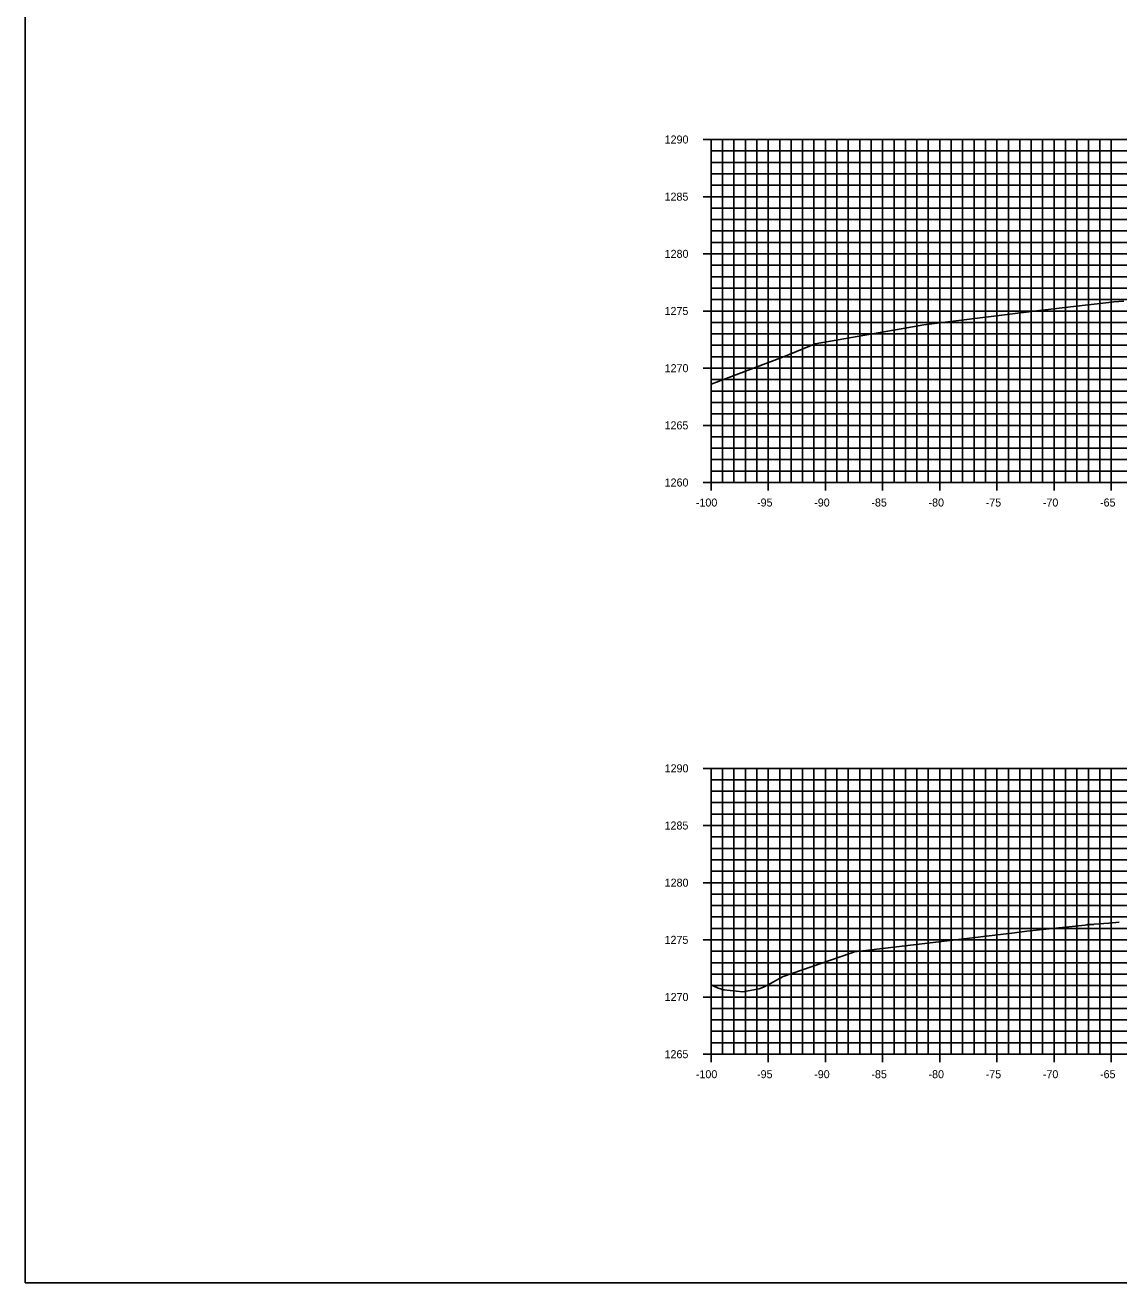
# Model space of a CAD drawing. Extents: x 674939 to 678919, y 750652 to 765176.
# Drawn here: x 678578.5 to 678674.2, y 756212.6 to 756322.6 of the extents above; entities that cross this region are included whole.
import ezdxf

# ---------------------------------------------------------------- set-up
doc = ezdxf.new("R2010")
doc.units = 0
for name, color, linetype in [('Level 10', 7, 'Continuous'), ('Level 20', 7, 'Continuous'), ('Level 4', 7, 'Continuous'), ('Level 8', 7, 'Continuous'), ('Level 9', 7, 'Continuous')]:
    doc.layers.add(name, color=color, linetype=linetype)

msp = doc.modelspace()

# ---------------------------------------------------------------- linework, layer by layer
at = {"layer": 'Level 10'}
for points in [[(678638.53, 756291.15), (678644.85, 756293.54), (678647.63, 756294.67), (678655.17, 756295.98), (678657.14, 756296.33), (678657.84, 756296.42), (678667.03, 756297.57), (678669.97, 756297.92), (678673.58, 756298.32), (678673.75, 756298.34), (678674.63, 756298.4)], [(678638.53, 756238.63), (678638.71, 756238.54), (678639.14, 756238.31), (678639.64, 756238.18), (678641.3, 756238), (678642.73, 756238.28), (678643.12, 756238.41), (678643.41, 756238.57), (678644.83, 756239.35), (678650.67, 756241.35), (678651.07, 756241.49), (678665.08, 756243.17), (678666.15, 756243.31), (678668.11, 756243.52), (678671.25, 756243.84), (678671.39, 756243.87), (678671.47, 756243.88), (678672.01, 756243.9), (678672.05, 756243.91), (678673.31, 756244.02), (678674.22, 756244.09)]]:
    msp.add_lwpolyline(points, dxfattribs=at)
at = {"layer": 'Level 20'}
for p, q in [((678638.53, 756312.55), (678838.53, 756312.55)), ((678638.53, 756282.55), (678638.53, 756312.55)), ((678639.53, 756282.55), (678639.53, 756312.55)), ((678640.53, 756282.55), (678640.53, 756312.55)), ((678641.53, 756282.55), (678641.53, 756312.55)), ((678642.53, 756282.55), (678642.53, 756312.55)), ((678643.53, 756282.55), (678643.53, 756312.55)), ((678644.53, 756282.55), (678644.53, 756312.55)), ((678645.53, 756282.55), (678645.53, 756312.55)), ((678646.53, 756282.55), (678646.53, 756312.55)), ((678647.53, 756282.55), (678647.53, 756312.55)), ((678648.53, 756282.55), (678648.53, 756312.55)), ((678649.53, 756282.55), (678649.53, 756312.55)), ((678650.53, 756282.55), (678650.53, 756312.55)), ((678651.53, 756282.55), (678651.53, 756312.55)), ((678652.53, 756282.55), (678652.53, 756312.55)), ((678653.53, 756282.55), (678653.53, 756312.55)), ((678654.53, 756282.55), (678654.53, 756312.55)), ((678655.53, 756282.55), (678655.53, 756312.55)), ((678656.53, 756282.55), (678656.53, 756312.55)), ((678657.53, 756282.55), (678657.53, 756312.55)), ((678658.53, 756282.55), (678658.53, 756312.55)), ((678659.53, 756282.55), (678659.53, 756312.55)), ((678660.53, 756282.55), (678660.53, 756312.55)), ((678661.53, 756282.55), (678661.53, 756312.55)), ((678662.53, 756282.55), (678662.53, 756312.55)), ((678663.53, 756282.55), (678663.53, 756312.55)), ((678664.53, 756282.55), (678664.53, 756312.55)), ((678665.53, 756282.55), (678665.53, 756312.55)), ((678666.53, 756282.55), (678666.53, 756312.55)), ((678667.53, 756282.55), (678667.53, 756312.55)), ((678668.53, 756282.55), (678668.53, 756312.55)), ((678669.53, 756282.55), (678669.53, 756312.55)), ((678670.53, 756282.55), (678670.53, 756312.55)), ((678671.53, 756282.55), (678671.53, 756312.55)), ((678672.53, 756282.55), (678672.53, 756312.55)), ((678673.53, 756282.55), (678673.53, 756312.55)), ((678638.53, 756311.55), (678838.53, 756311.55)), ((678638.53, 756310.55), (678838.53, 756310.55)), ((678638.53, 756309.55), (678838.53, 756309.55)), ((678638.53, 756308.55), (678838.53, 756308.55)), ((678638.53, 756307.55), (678838.53, 756307.55)), ((678638.53, 756306.55), (678838.53, 756306.55)), ((678638.53, 756305.55), (678838.53, 756305.55)), ((678638.53, 756304.55), (678838.53, 756304.55)), ((678638.53, 756303.55), (678838.53, 756303.55)), ((678638.53, 756302.55), (678838.53, 756302.55)), ((678638.53, 756301.55), (678838.53, 756301.55)), ((678638.53, 756300.55), (678838.53, 756300.55)), ((678638.53, 756299.55), (678838.53, 756299.55)), ((678638.53, 756298.55), (678838.53, 756298.55)), ((678638.53, 756297.55), (678838.53, 756297.55)), ((678638.53, 756296.55), (678838.53, 756296.55)), ((678638.53, 756295.55), (678838.53, 756295.55)), ((678638.53, 756294.55), (678838.53, 756294.55)), ((678638.53, 756293.55), (678838.53, 756293.55)), ((678638.53, 756292.55), (678838.53, 756292.55)), ((678638.53, 756291.55), (678838.53, 756291.55)), ((678638.53, 756290.55), (678838.53, 756290.55)), ((678638.53, 756289.55), (678838.53, 756289.55)), ((678638.53, 756288.55), (678838.53, 756288.55)), ((678638.53, 756287.55), (678838.53, 756287.55)), ((678638.53, 756286.55), (678838.53, 756286.55)), ((678638.53, 756285.55), (678838.53, 756285.55)), ((678638.53, 756284.55), (678838.53, 756284.55)), ((678638.53, 756283.55), (678838.53, 756283.55)), ((678638.53, 756282.55), (678838.53, 756282.55)), ((678638.53, 756257.55), (678838.53, 756257.55)), ((678638.53, 756232.55), (678638.53, 756257.55)), ((678639.53, 756232.55), (678639.53, 756257.55)), ((678640.53, 756232.55), (678640.53, 756257.55)), ((678641.53, 756232.55), (678641.53, 756257.55)), ((678642.53, 756232.55), (678642.53, 756257.55)), ((678643.53, 756232.55), (678643.53, 756257.55)), ((678644.53, 756232.55), (678644.53, 756257.55)), ((678645.53, 756232.55), (678645.53, 756257.55)), ((678646.53, 756232.55), (678646.53, 756257.55)), ((678647.53, 756232.55), (678647.53, 756257.55)), ((678648.53, 756232.55), (678648.53, 756257.55)), ((678649.53, 756232.55), (678649.53, 756257.55)), ((678650.53, 756232.55), (678650.53, 756257.55)), ((678651.53, 756232.55), (678651.53, 756257.55)), ((678652.53, 756232.55), (678652.53, 756257.55)), ((678653.53, 756232.55), (678653.53, 756257.55)), ((678654.53, 756232.55), (678654.53, 756257.55)), ((678655.53, 756232.55), (678655.53, 756257.55)), ((678656.53, 756232.55), (678656.53, 756257.55)), ((678657.53, 756232.55), (678657.53, 756257.55)), ((678658.53, 756232.55), (678658.53, 756257.55)), ((678659.53, 756232.55), (678659.53, 756257.55)), ((678660.53, 756232.55), (678660.53, 756257.55)), ((678661.53, 756232.55), (678661.53, 756257.55)), ((678662.53, 756232.55), (678662.53, 756257.55)), ((678663.53, 756232.55), (678663.53, 756257.55)), ((678664.53, 756232.55), (678664.53, 756257.55)), ((678665.53, 756232.55), (678665.53, 756257.55)), ((678666.53, 756232.55), (678666.53, 756257.55)), ((678667.53, 756232.55), (678667.53, 756257.55)), ((678668.53, 756232.55), (678668.53, 756257.55)), ((678669.53, 756232.55), (678669.53, 756257.55)), ((678670.53, 756232.55), (678670.53, 756257.55)), ((678671.53, 756232.55), (678671.53, 756257.55)), ((678672.53, 756232.55), (678672.53, 756257.55)), ((678673.53, 756232.55), (678673.53, 756257.55)), ((678638.53, 756256.55), (678838.53, 756256.55)), ((678638.53, 756255.55), (678838.53, 756255.55)), ((678638.53, 756254.55), (678838.53, 756254.55)), ((678638.53, 756253.55), (678838.53, 756253.55)), ((678638.53, 756252.55), (678838.53, 756252.55)), ((678638.53, 756251.55), (678838.53, 756251.55)), ((678638.53, 756250.55), (678838.53, 756250.55)), ((678638.53, 756249.55), (678838.53, 756249.55)), ((678638.53, 756248.55), (678838.53, 756248.55)), ((678638.53, 756247.55), (678838.53, 756247.55)), ((678638.53, 756246.55), (678838.53, 756246.55)), ((678638.53, 756245.55), (678838.53, 756245.55)), ((678638.53, 756244.55), (678838.53, 756244.55)), ((678638.53, 756243.55), (678838.53, 756243.55)), ((678638.53, 756242.55), (678838.53, 756242.55)), ((678638.53, 756241.55), (678838.53, 756241.55)), ((678638.53, 756240.55), (678838.53, 756240.55)), ((678638.53, 756239.55), (678838.53, 756239.55)), ((678638.53, 756238.55), (678838.53, 756238.55)), ((678638.53, 756237.55), (678838.53, 756237.55)), ((678638.53, 756236.55), (678838.53, 756236.55)), ((678638.53, 756235.55), (678838.53, 756235.55)), ((678638.53, 756234.55), (678838.53, 756234.55)), ((678638.53, 756233.55), (678838.53, 756233.55)), ((678638.53, 756232.55), (678838.53, 756232.55))]:
    msp.add_line(p, q, dxfattribs=at)
at = {"layer": 'Level 4'}
msp.add_lwpolyline([(678578.53, 756212.55), (678918.53, 756212.55), (678918.53, 756432.55), (678578.53, 756432.55)], close=True, dxfattribs=at)
at = {"layer": 'Level 8'}
for p, q in [((678637.83, 756312.55), (678639.23, 756312.55)), ((678638.53, 756282.55), (678638.53, 756312.55)), ((678638.53, 756311.55), (678638.88, 756311.55)), ((678638.53, 756310.55), (678638.88, 756310.55)), ((678638.53, 756309.55), (678638.88, 756309.55)), ((678638.53, 756308.55), (678638.88, 756308.55)), ((678637.83, 756307.55), (678639.23, 756307.55)), ((678638.53, 756306.55), (678638.88, 756306.55)), ((678638.53, 756305.55), (678638.88, 756305.55)), ((678638.53, 756304.55), (678638.88, 756304.55)), ((678638.53, 756303.55), (678638.88, 756303.55)), ((678637.83, 756302.55), (678639.23, 756302.55)), ((678638.53, 756301.55), (678638.88, 756301.55)), ((678638.53, 756300.55), (678638.88, 756300.55)), ((678638.53, 756299.55), (678638.88, 756299.55)), ((678638.53, 756298.55), (678638.88, 756298.55)), ((678637.83, 756297.55), (678639.23, 756297.55)), ((678638.53, 756296.55), (678638.88, 756296.55)), ((678638.53, 756295.55), (678638.88, 756295.55)), ((678638.53, 756294.55), (678638.88, 756294.55)), ((678638.53, 756293.55), (678638.88, 756293.55)), ((678637.83, 756292.55), (678639.23, 756292.55)), ((678638.53, 756291.55), (678638.88, 756291.55)), ((678638.53, 756290.55), (678638.88, 756290.55)), ((678638.53, 756289.55), (678638.88, 756289.55)), ((678638.53, 756288.55), (678638.88, 756288.55)), ((678637.83, 756287.55), (678639.23, 756287.55)), ((678638.53, 756286.55), (678638.88, 756286.55)), ((678638.53, 756285.55), (678638.88, 756285.55)), ((678638.53, 756284.55), (678638.88, 756284.55)), ((678638.53, 756283.55), (678638.88, 756283.55)), ((678638.53, 756281.85), (678638.53, 756283.25)), ((678643.53, 756281.85), (678643.53, 756283.25)), ((678648.53, 756281.85), (678648.53, 756283.25)), ((678653.53, 756281.85), (678653.53, 756283.25)), ((678658.53, 756281.85), (678658.53, 756283.25)), ((678663.53, 756281.85), (678663.53, 756283.25)), ((678668.53, 756281.85), (678668.53, 756283.25)), ((678673.53, 756281.85), (678673.53, 756283.25)), ((678637.83, 756282.55), (678639.23, 756282.55)), ((678638.53, 756282.55), (678838.53, 756282.55)), ((678637.83, 756257.55), (678639.23, 756257.55)), ((678638.53, 756232.55), (678638.53, 756257.55)), ((678638.53, 756256.55), (678638.88, 756256.55)), ((678638.53, 756255.55), (678638.88, 756255.55)), ((678638.53, 756254.55), (678638.88, 756254.55)), ((678638.53, 756253.55), (678638.88, 756253.55)), ((678637.83, 756252.55), (678639.23, 756252.55)), ((678638.53, 756251.55), (678638.88, 756251.55)), ((678638.53, 756250.55), (678638.88, 756250.55)), ((678638.53, 756249.55), (678638.88, 756249.55)), ((678638.53, 756248.55), (678638.88, 756248.55)), ((678637.83, 756247.55), (678639.23, 756247.55)), ((678638.53, 756246.55), (678638.88, 756246.55)), ((678638.53, 756245.55), (678638.88, 756245.55)), ((678638.53, 756244.55), (678638.88, 756244.55)), ((678638.53, 756243.55), (678638.88, 756243.55)), ((678637.83, 756242.55), (678639.23, 756242.55)), ((678638.53, 756241.55), (678638.88, 756241.55)), ((678638.53, 756240.55), (678638.88, 756240.55)), ((678638.53, 756239.55), (678638.88, 756239.55)), ((678638.53, 756238.55), (678638.88, 756238.55)), ((678637.83, 756237.55), (678639.23, 756237.55)), ((678638.53, 756236.55), (678638.88, 756236.55)), ((678638.53, 756235.55), (678638.88, 756235.55)), ((678638.53, 756234.55), (678638.88, 756234.55)), ((678638.53, 756233.55), (678638.88, 756233.55)), ((678637.83, 756232.55), (678639.23, 756232.55)), ((678638.53, 756231.85), (678638.53, 756233.25)), ((678638.53, 756232.55), (678838.53, 756232.55)), ((678643.53, 756231.85), (678643.53, 756233.25)), ((678648.53, 756231.85), (678648.53, 756233.25)), ((678653.53, 756231.85), (678653.53, 756233.25)), ((678658.53, 756231.85), (678658.53, 756233.25)), ((678663.53, 756231.85), (678663.53, 756233.25)), ((678668.53, 756231.85), (678668.53, 756233.25)), ((678673.53, 756231.85), (678673.53, 756233.25))]:
    msp.add_line(p, q, dxfattribs=at)

# ---------------------------------------------------------------- texts
at = {"layer": 'Level 9'}
for s, p in [('1290', (678634.47, 756312.2)), ('1285', (678634.46, 756307.2)), ('1280', (678634.47, 756302.2)), ('1275', (678634.46, 756297.2)), ('1270', (678634.47, 756292.2)), ('1265', (678634.46, 756287.2)), ('1260', (678634.47, 756282.2)), ('-100', (678637.2, 756280.45)), ('-95', (678642.55, 756280.45)), ('-90', (678647.55, 756280.45)), ('-85', (678652.55, 756280.45)), ('-80', (678657.55, 756280.45)), ('-75', (678662.55, 756280.45)), ('-70', (678667.55, 756280.45)), ('-65', (678672.55, 756280.45)), ('1290', (678634.47, 756257.2)), ('1285', (678634.46, 756252.2)), ('1280', (678634.47, 756247.2)), ('1275', (678634.46, 756242.2)), ('1270', (678634.47, 756237.2)), ('1265', (678634.46, 756232.2)), ('-100', (678637.2, 756230.45)), ('-95', (678642.55, 756230.45)), ('-90', (678647.55, 756230.45)), ('-85', (678652.55, 756230.45)), ('-80', (678657.55, 756230.45)), ('-75', (678662.55, 756230.45)), ('-70', (678667.55, 756230.45)), ('-65', (678672.55, 756230.45))]:
    msp.add_text(s, height=0.7, dxfattribs=at).set_placement(p)

doc.saveas('drawing.dxf')
